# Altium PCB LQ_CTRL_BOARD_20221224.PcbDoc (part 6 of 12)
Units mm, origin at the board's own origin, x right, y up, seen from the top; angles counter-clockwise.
Board outline 260 x 142 mm, 6 copper layers (Top Layer, Mid-Layer 1, Mid-Layer 2, Mid-Layer 3, Mid-Layer 4, Bottom Layer); 1105 components, 1039 nets, 3898 pads, 1277 vias.
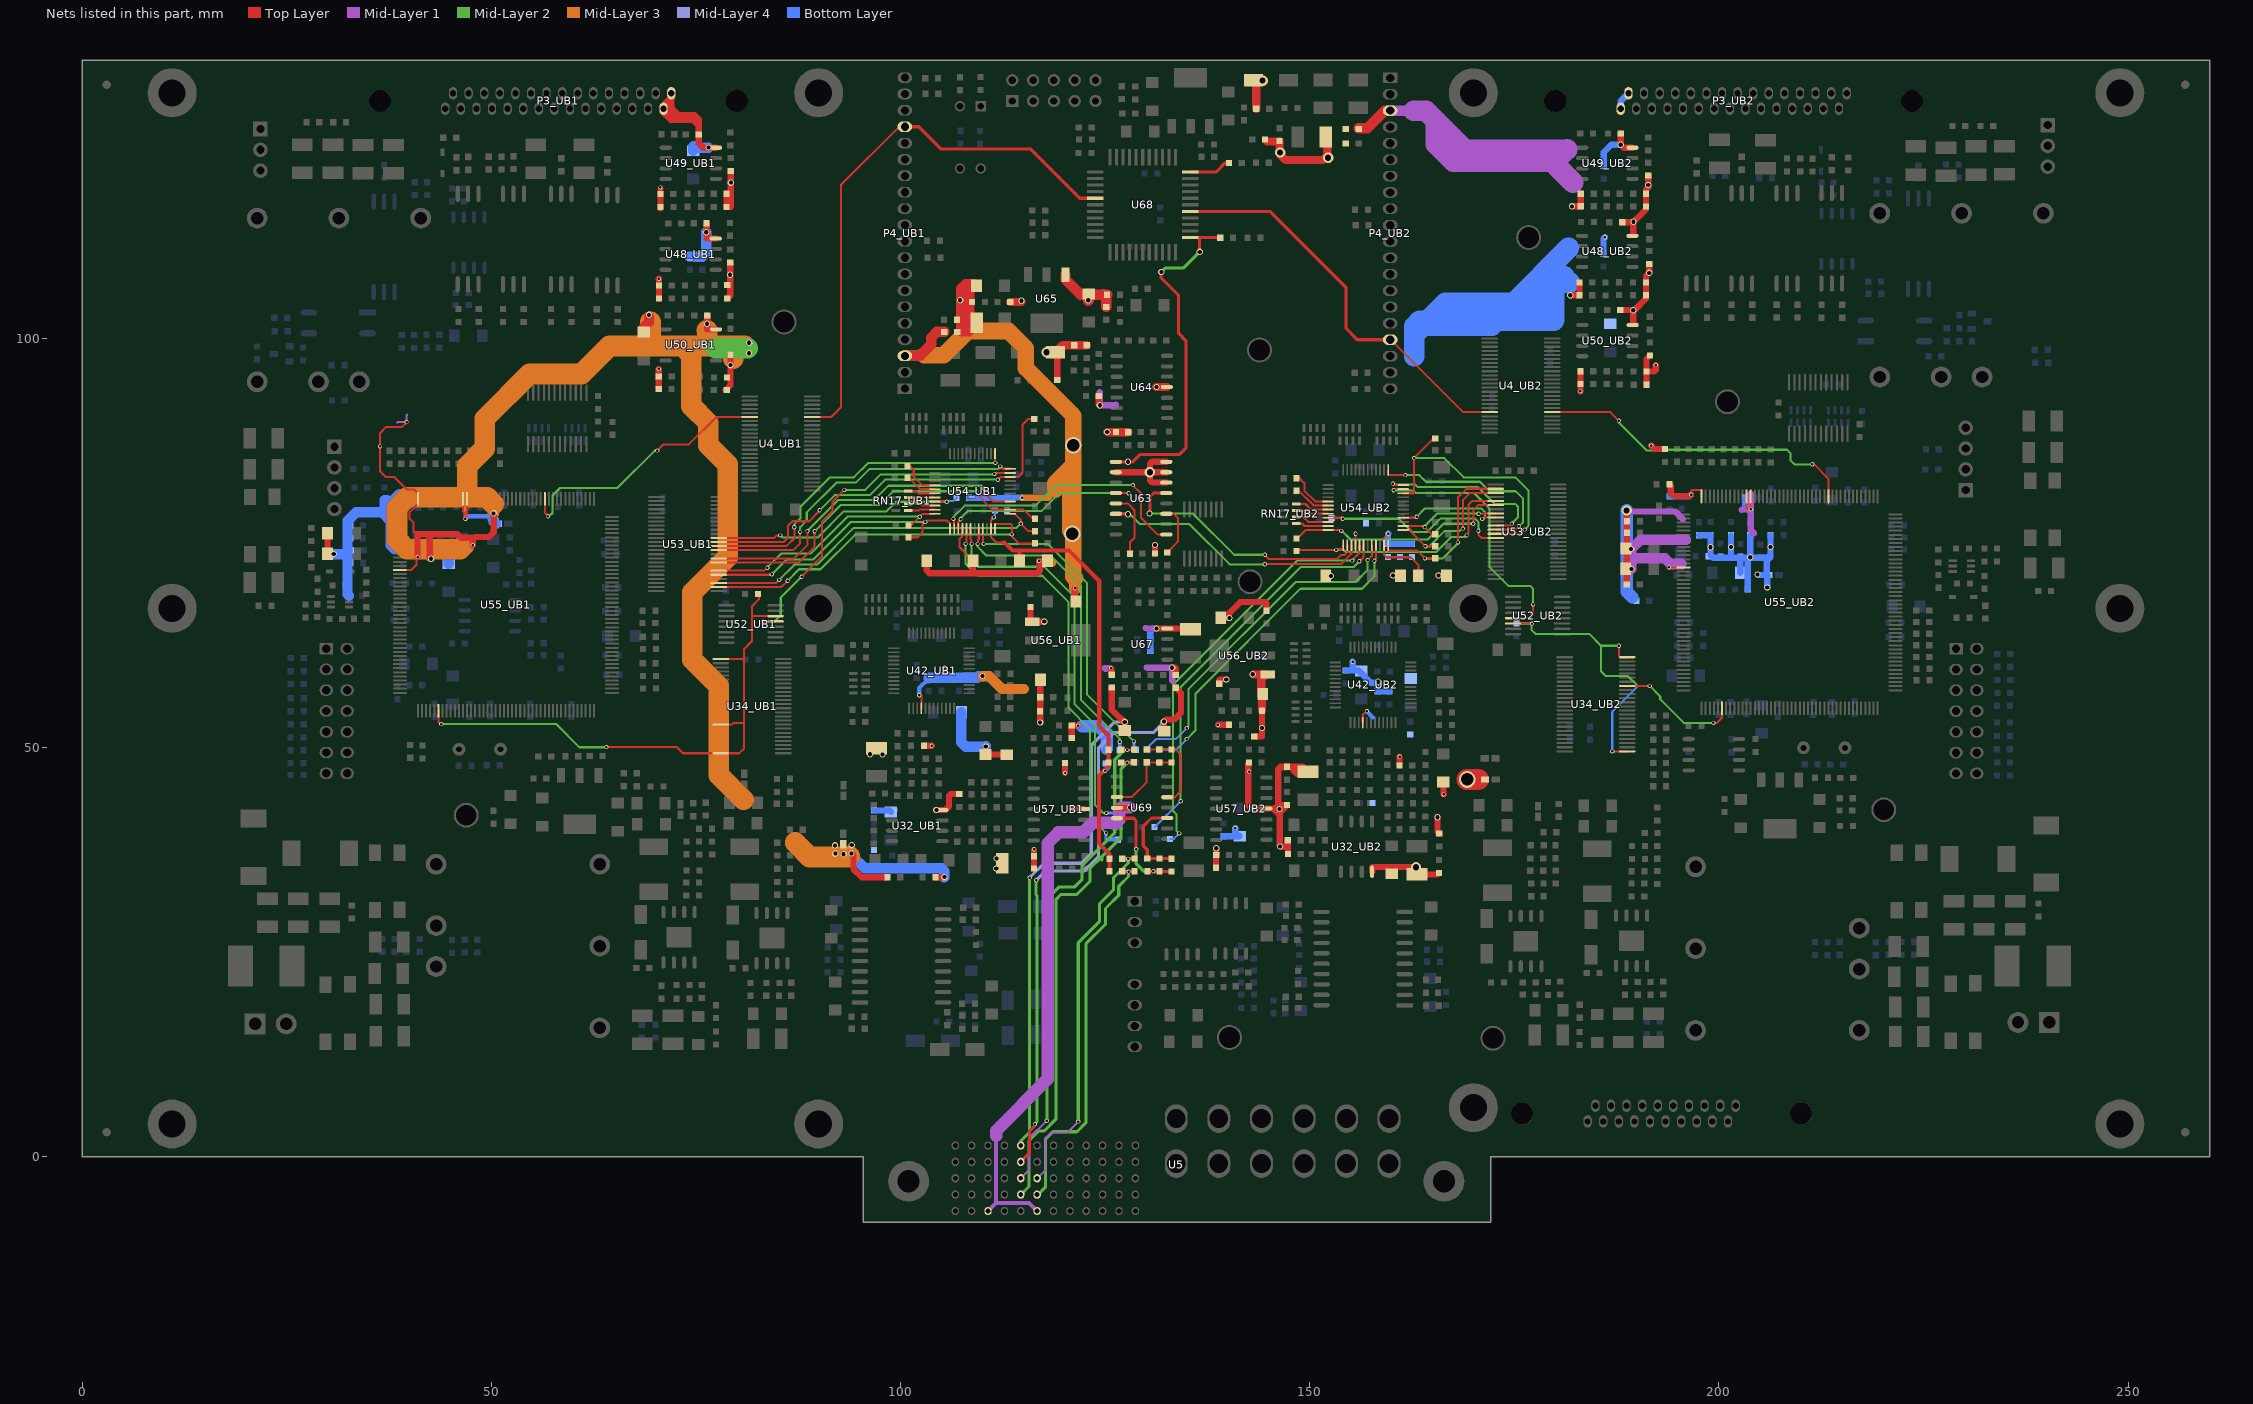
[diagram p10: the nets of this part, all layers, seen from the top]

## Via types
v1: diameter 0.508, hole 0.305, Top Layer to Bottom Layer, 845 vias
v2: diameter 0.762, hole 0.508, Top Layer to Bottom Layer, 317 vias
v3: diameter 1.27, hole 0.762, Top Layer to Bottom Layer, 77 vias
v4: diameter 2.032, hole 1.524, Top Layer to Bottom Layer, 15 vias
v5: diameter 2.032, hole 1.27, Top Layer to Bottom Layer, 11 vias
v6: diameter 1.27, hole 0.711, Top Layer to Bottom Layer, 8 vias
v7: diameter 2.54, hole 1.778, Top Layer to Bottom Layer, 3 vias
v8: diameter 1.524, hole 1.016, Top Layer to Bottom Layer, 1 vias

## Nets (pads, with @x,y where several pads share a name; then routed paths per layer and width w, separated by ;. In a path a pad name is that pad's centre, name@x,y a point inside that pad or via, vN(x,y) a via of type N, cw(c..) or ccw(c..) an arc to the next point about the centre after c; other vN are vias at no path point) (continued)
AGND_UB1: C1_UB1.1 C2_UB1.1 C242_UB1.2 C259_UB1.2 C260_UB1.2 C261_UB1.2 C262_UB1.2 C267_UB1.2 C268_UB1.2 C284_UB1.2 C285_UB1.1 C286_UB1.2 C287_UB1.2 C288_UB1.2 C289_UB1.2 C299_UB1.1 C300_UB1.1 C301_UB1.1 C302_UB1.1 C303_UB1.1 C304_UB1.1 C311_UB1.2 C312_UB1.2 C319_UB1.1 C324_UB1.1 C325_UB1.1 C326_UB1.1 C327_UB1.2 C328_UB1.2 C329_UB1.1 C330_UB1.1 C343_UB1.1 C344_UB1.1 C345_UB1.1 C354_UB1.1 C355_UB1.1 C360_UB1.1 C361_UB1.1 C362_UB1.2 C363_UB1.2 C364_UB1.2 C365_UB1.2 C369_UB1.2 C370_UB1.2 C371_UB1.1 C372_UB1.1 C373_UB1.2 C374_UB1.1 C377_UB1.2 C378_UB1.2 C379_UB1.2 C380_UB1.2 C381_UB1.2 C382_UB1.2 C389_UB1.2 C392_UB1.2 C393_UB1.2 C394_UB1.2 C395_UB1.2 C396_UB1.2 C397_UB1.2 C398_UB1.2 C399_UB1.2 C400_UB1.2 P3_UB1.15 P3_UB1.30 P4_UB1.3 R17_UB1.2 R18_UB1.2 R19_UB1.2 R20_UB1.2 R21_UB1.2 R22_UB1.2 R198_UB1.1 R216_UB1.2 R231_UB1.1 R296_UB1.1 R299_UB1.2 R325_UB1.1 R328_UB1.1 R330_UB1.1 R341_UB1.1 R342_UB1.1 R343_UB1.2 R344_UB1.2 R386.1 U32_UB1.4 U42_UB1.40 U48_UB1.4 U49_UB1.4 U50_UB1.4 U54_UB1.40 U55_UB1.32 U55_UB1.33 U55_UB1.44 U55_UB1.58 U56_UB1.1 U57_UB1.11 | length 534.2
  Top Layer w0.254: U55_UB1.58@38.84,71.691 40.22,71.691 40.869,72.339 v1@40.869,73.279 ; v1@39.7,89.764 39.116,89.179 37.16,89.179 36.398,88.417 36.398,83.769 37.135,83.033 38.176,83.033 39.7,81.509 40.589,81.509 ; 40.589,81.534 40.589,81.509 ; U55_UB1.44@41.04,79.674 U55_UB1.44@41.04,79.775 ; U55_UB1.33@46.54,80.391 46.533,80.384 46.533,78.867 46.711,78.689 ; 46.66,78.689 46.711,78.689 ; v1@46.838,77.851 v1(46.838,77.927) 46.838,78.638 ; U55_UB1.32@47.04,80.391 47.04,78.702 47.027,78.689 46.711,78.689 ; v1(102.286,56.394) 102.301,56.379 102.549,56.379 U42_UB1.40@102.549,54.785 ; U54_UB1.40@107.563,76.71 107.563,75.839 107.213,75.489 107.213,74.498 108.864,72.847 C369_UB1.2@108.864,72.822 ; 40.589,81.509 41.04,81.058 U55_UB1.44@41.04,80.391 U55_UB1.44@41.04,79.775 ; v1@40.869,73.279 40.869,76.098 40.97,76.2 ; v1@40.869,73.279 40.97,73.381 40.97,76.2 ; 40.97,76.2 40.97,76.302 ; 40.97,76.2 41.021,76.251 40.97,76.302 ; 40.97,76.302 40.513,76.302 40.513,77.445 40.02,77.937 40.02,78.755 U55_UB1.44@41.04,79.775
  Top Layer w0.762: C381_UB1.2@29.98,73.66 C382_UB1.2@29.98,76.2 ; C381_UB1.2@30.142,73.635 v2(30.759,73.635) ; v1(40.996,73.279) 40.996,75.87 41.173,76.048 42.494,76.048 ; v2(42.621,73.076) 42.494,73.203 42.494,76.048 ; v1(47.727,74.727) 47.727,75.387 47.981,75.641 ; v2(50.292,78.613) 50.292,76.302 49.708,75.717 48.057,75.717 47.981,75.641 ; v1(70.46,96.266) 70.465,96.261 R19_UB1.2@70.465,95.326 C301_UB1.1@70.465,93.878 ; v1@70.465,107.29 v1(70.485,107.27) R21_UB1.2@70.485,106.451 C299_UB1.1@70.485,104.877 ; C324_UB1.1@70.663,115.875 v1@70.663,118.237 ; C324_UB1.1@70.663,116.078 C324_UB1.1@70.688,116.053 ; P3_UB1.15@71.044,128.047 71.044,127.584 71.323,127.305 ; P3_UB1.30@71.996,129.952 P3_UB1.30@71.996,129.464 ; C302_UB1.1@76.332,114.071 76.332,112.192 U48_UB1.4@77.425,112.192 ; C304_UB1.1@76.403,102.794 76.403,101.092 U50_UB1.4@77.45,101.092 ; v2(76.53,123.302) v2@76.54,123.292 ; U49_UB1.4@77.472,123.302 U49_UB1.4@77.462,123.292 v2@76.54,123.292 ; C325_UB1.1@78.644,93.675 79.223,94.254 v2(79.223,96.723) C330_UB1.1@79.223,97.993 ; C319_UB1.1@78.842,104.877 79.197,105.232 C326_UB1.1@79.197,109.271 ; 79.273,117.856 C303_UB1.1@79.273,120.447 ; v2(94.021,37.059) 94.259,36.82 94.259,35.154 95.275,34.138 R216_UB1.2@98.389,34.138 ; C242_UB1.2@102.87,50.216 v1(103.81,50.216) ; C373_UB1.2@103.2,72.796 103.2,71.646 103.549,71.298 108.966,71.298 ; R198_UB1.1@104.267,34.163 v2(105.359,34.163) ; U32_UB1.4@104.383,42.367 U32_UB1.4@105.12,42.367 105.475,42.367 105.933,42.824 105.933,44.134 106.121,44.323 C261_UB1.2@107.188,44.323 ; C369_UB1.2@108.864,72.822 108.864,71.399 108.966,71.298 ; v2(110.414,50.14) 110.388,50.114 C267_UB1.2@110.388,49.149 112.986,49.149 C259_UB1.2@113.011,49.124 ; C395_UB1.2@115.895,67.183 115.895,65.583 U56_UB1.1@116.098,65.38 v2(117.577,65.38) ; R343_UB1.2@116.307,35.204 v1@116.307,37.465 ; v1(116.942,72.801) v1@116.946,72.796 ; v2(117.069,53.061) 117.089,53.081 C396_UB1.2@117.089,56.134 C394_UB1.2@117.089,58.293 ; C362_UB1.2@117.958,72.796 v1@116.946,72.796 ; v1(120.117,46.888) R344_UB1.2@120.117,48.108 ; R341_UB1.1@120.929,51.156 C397_UB1.2@120.929,52.68 v1(121.717,52.68) ; v1(121.082,42.52) 121.107,42.494 U57_UB1.11@122.423,42.494 ; v1@121.285,69.367 121.285,67.965 C393_UB1.2@121.407,67.843 ; 42.494,76.048 45.872,76.048 46.279,75.641 47.981,75.641 ; 71.323,127.305 71.323,128.791 P3_UB1.30@71.996,129.464 ; 71.323,127.305 71.933,126.695 72.492,126.695 ; 71.996,128.156 71.996,127.191 72.492,126.695 ; 71.996,128.156 P3_UB1.30@71.996,129.464 ; 71.996,128.156 72.898,127.254 74.835,127.254 ; 72.492,126.695 74.835,126.695 ; 74.835,126.695 74.835,127.254 ; 74.835,126.695 74.835,126.511 75.342,126.004 ; 74.835,126.695 75.089,126.695 75.342,126.442 ; 74.835,127.254 75.342,126.747 75.342,126.442 ; 75.342,126.004 75.342,126.442 ; 75.342,126.004 C329_UB1.1@75.342,124.917 75.342,123.845 75.895,123.292 v2@76.54,123.292 ; 108.966,71.298 116.713,71.298 117.018,71.603 117.018,72.725 v1@116.946,72.796 ; C300_UB1.1@78.745,116.053 R17_UB1.2@78.745,117.678 79.273,117.678 79.299,117.704 79.299,116.103 79.248,116.053 C300_UB1.1@78.745,116.053
  Top Layer w1.27: C312_UB1.2@68.605,100.762 68.605,101.295 69.266,101.956 v2@69.266,102.616 ; P4_UB1.3@100.533,97.853 102.349,97.853 103.759,99.263 103.759,100.101 104.445,100.787 R386.1@105.359,100.787
  Mid-Layer 1 w0.254: 38.506,89.713 38.557,89.764 v1(39.649,89.764) 39.649,90.627 39.7,90.678 39.7,90.703
  Mid-Layer 2 w2.54: 77.445,98.781 81.305,98.781
  Mid-Layer 3 w0.508: v1(46.838,77.927) 46.838,79.604 47.828,80.594
  Mid-Layer 3 w0.762: v1(114.859,80.518) 118.11,80.518 118.161,80.569 ; v1(116.942,72.801) 118.36,72.801 118.643,72.517
  Mid-Layer 3 w1.27: v2(50.292,78.613) 50.292,79.766 ; P4_UB1.3@100.533,97.853 102.806,97.853 102.895,97.942 ; v2(110.033,58.725) 110.846,58.725 112.42,57.15 115.062,57.15
  Mid-Layer 3 w1.524: 121.107,84.48 121.082,84.455 121.082,82.372 120.498,81.788 120.498,78.858 ; v1(121.336,69.444) 121.336,70.663 v4@121.336,75.565 ; 120.498,78.858 121.107,78.248 121.336,78.02 v4@121.336,75.565 ; 120.498,78.858 120.498,76.403 121.107,75.794 v4@121.336,75.565
  Mid-Layer 3 w2.032: 102.895,97.942 105.308,97.942 108.255,100.889 113.208,100.889 115.316,98.781 115.316,96.342 121.107,90.551 121.107,84.48 121.107,82.398 ; 118.897,81.509 118.897,82.271 121.082,84.455 ; 121.082,82.372 121.107,82.398 ; 121.336,70.663 121.107,70.891 121.107,75.794 121.107,78.248 121.107,82.398
  Mid-Layer 3 w2.54: 46.702,74.727 46.204,74.229 39.665,74.229 38.481,75.413 38.481,79.299 39.776,80.594 47.828,80.594 ; 49.062,86.447 49.062,86.4 ; 50.292,79.766 49.464,80.594 47.828,80.594 ; 69.444,101.981 69.444,99.162 69.342,99.06 ; 76.352,100.94 76.378,100.914 76.378,99.06 ; 79.578,97.536 79.578,98.349 78.867,99.06 ; 80.823,43.612 77.8,46.634 77.8,57.506 74.549,60.757 74.549,68.936 78.892,73.279 78.892,84.582 76.505,86.97 76.505,89.687 74.447,91.745 74.447,97.997 73.99,98.455 73.99,99.06 ; 81.026,99.009 80.975,99.06 78.867,99.06 ; 87.147,38.379 88.9,36.627 93.675,36.627 93.777,36.728 ; 47.828,80.594 47.066,81.356 47.066,84.404 49.062,86.4 ; 49.062,86.4 49.2,86.538 49.2,90.17 54.686,95.656 61.036,95.656 64.44,99.06 69.342,99.06 ; 69.342,99.06 73.99,99.06 ; 73.99,99.06 76.378,99.06 ; 76.378,99.06 78.867,99.06
  Bottom Layer w0.508: v1(46.838,77.927) 46.838,77.953 47.142,78.257 49.733,78.257 v2@50.19,78.715 ; v1(102.286,56.394) 102.286,57.252 103.429,58.395 C285_UB1.1@103.429,58.471 ; C268_UB1.2@105.004,58.522 105.385,58.903 v1(105.385,59.754)
  Bottom Layer w0.762: C355_UB1.1@40.97,74.041 C355_UB1.1@40.742,74.27 C355_UB1.1@40.996,74.27 ; v1@40.996,73.381 C355_UB1.1@40.996,74.27 ; 42.621,74.27 C372_UB1.1@42.24,74.27 C355_UB1.1@40.996,74.27 ; 42.774,74.27 44.907,74.27 45.187,74.27 C1_UB1.1@45.212,74.295 ; C400_UB1.2@46.761,74.295 46.761,74.346 47.092,74.676 v1@47.6,74.676 ; C287_UB1.2@96.774,42.291 98.679,42.291 C289_UB1.2@98.831,42.139 ; C374_UB1.1@108.382,80.518 108.42,80.48 112.967,80.48 C364_UB1.2@113.03,80.543 114.833,80.543 v1(114.859,80.518)
  Bottom Layer w1.27: v2(30.759,73.635) 32.436,73.635 ; R299_UB1.2@32.614,68.555 32.436,68.732 32.436,73.635 ; 37.719,79.888 38.781,80.95 R328_UB1.1@39.7,80.95 ; R328_UB1.1@39.548,80.874 C361_UB1.1@41.072,80.874 46.126,80.874 ; v2@42.621,73.33 42.621,74.27 ; C398_UB1.2@44.78,72.466 44.78,74.143 44.907,74.27 C1_UB1.1@44.933,74.295 ; C2_UB1.1@45.695,80.95 48.616,80.95 C345_UB1.1@48.666,80.899 49.784,80.899 50.19,80.493 50.19,78.715 v2(50.292,78.613) ; C400_UB1.2@46.761,74.295 C1_UB1.1@45.212,74.295 C1_UB1.1@44.933,74.295 ; v2@50.19,78.384 50.19,77.95 50.292,77.848 50.292,77.607 R296_UB1.1@50.543,77.356 ; C328_UB1.2@74.27,109.957 C327_UB1.2@75.783,109.957 76.276,110.45 v2(76.276,112.954) ; C311_UB1.2@74.651,122.911 74.651,123.393 74.727,123.469 74.894,123.302 v2(76.53,123.302) ; 92.329,36.703 94.158,36.703 94.158,36.678 95.606,35.23 C377_UB1.2@98.984,35.23 C378_UB1.2@100.508,35.23 105.004,35.23 105.359,34.874 v2(105.359,34.163) ; C285_UB1.1@103.429,58.471 103.48,58.522 C268_UB1.2@105.004,58.522 C262_UB1.2@107.137,58.522 C260_UB1.2@108.56,58.522 109.372,58.522 109.576,58.725 v2(110.033,58.725) ; C284_UB1.2@107.442,54.331 107.442,50.622 107.95,50.114 110.388,50.114 v2(110.414,50.14) ; 32.436,73.635 32.436,77.699 33.477,78.74 36.652,78.74 ; 36.652,78.74 37.719,77.673 ; 36.652,78.74 36.703,78.74 ; 36.703,78.74 37.059,78.74 ; 36.703,78.74 36.957,78.994 ; 36.957,78.994 36.957,78.842 37.059,78.74 ; 36.957,78.994 C343_UB1.1@36.957,80.213 37.262,80.213 37.719,79.756 ; 36.957,78.994 37.719,79.756 ; 37.059,78.74 37.719,79.4 ; 37.719,77.673 37.719,74.727 38.151,74.295 C360_UB1.1@43.713,74.295 C1_UB1.1@44.933,74.295 ; 37.719,77.673 37.719,79.4 ; 37.719,79.4 37.719,79.756
  Bottom Layer w1.524: 122.225,52.578 124.206,52.578 125.222,51.562 C365_UB1.2@125.222,49.86
  other v1: 116.332,37.567 36.424,86.792 70.663,118.44
  other v2: 111.709,35.23 111.749,36.437 93.055,36.957 92.039,37.033 92.014,38.049 94.046,38.075 104.383,42.381 97.79,49.149 96.266,49.174 81.483,98.171 81.509,99.466 76.352,101.778 69.266,102.87 79.172,107.772 79.273,119.024
  other v4: 121.006,76.123 121.133,86.919
AGND_UB2: C1_UB2.1 C2_UB2.1 C242_UB2.2 C259_UB2.2 C260_UB2.2 C261_UB2.2 C262_UB2.2 C267_UB2.2 C268_UB2.2 C284_UB2.2 C285_UB2.1 C286_UB2.2 C287_UB2.2 C288_UB2.2 C289_UB2.2 C299_UB2.1 C300_UB2.1 C301_UB2.1 C302_UB2.1 C303_UB2.1 C304_UB2.1 C311_UB2.2 C312_UB2.2 C319_UB2.1 C324_UB2.1 C325_UB2.1 C326_UB2.1 C327_UB2.2 C328_UB2.2 C329_UB2.1 C330_UB2.1 C343_UB2.1 C344_UB2.1 C345_UB2.1 C354_UB2.1 C355_UB2.1 C360_UB2.1 C361_UB2.1 C362_UB2.2 C363_UB2.2 C364_UB2.2 C365_UB2.2 C369_UB2.2 C370_UB2.2 C371_UB2.1 C372_UB2.1 C373_UB2.2 C374_UB2.1 C377_UB2.2 C378_UB2.2 C379_UB2.2 C380_UB2.2 C381_UB2.2 C382_UB2.2 C389_UB2.2 C392_UB2.2 C393_UB2.2 C394_UB2.2 C395_UB2.2 C396_UB2.2 C397_UB2.2 C398_UB2.2 C399_UB2.2 C400_UB2.2 P3_UB2.15 P3_UB2.30 P4_UB2.3 R17_UB2.2 R18_UB2.2 R19_UB2.2 R20_UB2.2 R21_UB2.2 R22_UB2.2 R198_UB2.1 R216_UB2.2 R231_UB2.1 R296_UB2.1 R299_UB2.2 R325_UB2.1 R328_UB2.1 R330_UB2.1 R341_UB2.1 R342_UB2.1 R343_UB2.2 R344_UB2.2 R388.1 U32_UB2.4 U42_UB2.40 U48_UB2.4 U49_UB2.4 U50_UB2.4 U54_UB2.40 U55_UB2.32 U55_UB2.33 U55_UB2.44 U55_UB2.58 U56_UB2.1 U57_UB2.11 | length 358.7
  Top Layer w0.254: U54_UB2.40@155.592,74.723 155.592,76.115 v1(155.6,76.123) ; U42_UB2.40@156.484,53.05 156.484,53.969 v1@156.947,54.432 ; v1@193.806,72.009 v1(193.904,72.009) U55_UB2.58@195.605,72.009 ; v1(196.596,80.899) 196.596,81.331 196.748,81.483 197.815,81.483 197.885,81.413 U55_UB2.44@197.885,80.696 ; U55_UB2.33@203.385,80.696 203.385,79.291 203.606,79.07 203.632,79.096 v1@203.911,79.096 ; U55_UB2.32@203.885,80.696 203.885,79.122 v1@203.911,79.096 ; v1@203.937,79.121 v1@203.911,79.096
  Top Layer w0.762: R343_UB2.2@138.557,35.306 138.557,36.83 R342_UB2.1@138.582,36.855 v2(138.582,37.694) ; v1(138.786,52.756) 138.811,52.781 C397_UB2.2@140.157,52.781 ; C396_UB2.2@138.938,57.785 138.938,58.191 139.048,58.301 v2(139.802,58.301) ; C393_UB2.2@139.13,65.862 v2@140.157,65.862 ; v2(140.183,65.837) v2@140.157,65.862 ; R344_UB2.2@142.596,48.184 142.494,48.082 142.494,42.875 142.824,42.545 v1(143.358,42.545) U57_UB2.11@144.704,42.545 145.542,42.545 ; R341_UB2.1@143.231,51.333 144.145,51.333 144.17,51.359 R330_UB2.1@144.17,54.487 ; C395_UB2.2@144.729,66.726 144.729,67.64 144.602,67.767 141.503,67.767 140.157,66.421 v2@140.157,65.862 ; v2(146.304,42.494) v2@146.253,42.545 ; R216_UB2.2@147.32,38.659 147.345,38.633 147.345,37.871 ; R198_UB2.1@147.345,36.982 147.345,37.871 ; U32_UB2.4@157.632,34.823 157.632,35.331 157.709,35.408 162.839,35.408 162.865,35.433 163.119,35.179 C288_UB2.2@163.119,34.493 165.633,34.493 C286_UB2.2@165.811,34.671 ; v2@160.147,71.044 v2(160.173,71.018) C369_UB2.2@161.112,71.018 ; C242_UB2.2@160.96,47.803 160.96,48.92 v1(160.985,48.895) ; v2(165.608,41.478) 165.608,39.726 C287_UB2.2@165.837,39.497 ; v2@165.71,71.044 v2(165.735,71.018) C362_UB2.2@166.7,71.018 ; C267_UB2.2@166.345,45.771 166.345,44.298 v1(166.37,44.272) ; v2(181.839,105.258) C299_UB2.1@182.956,105.258 R21_UB2.2@182.956,106.807 ; v2@182.27,116.129 C324_UB2.1@183.134,116.129 R18_UB2.2@183.134,117.653 ; R19_UB2.2@183.07,95.987 183.083,95.973 C301_UB2.1@183.083,94.412 v1(183.083,93.523) ; C304_UB2.1@187.935,103.454 189.687,103.454 191.084,104.851 C319_UB2.1@191.084,105.258 R22_UB2.2@191.084,106.832 191.084,107.594 v2(191.491,108.001) C326_UB2.1@191.491,109.093 ; C329_UB2.1@188.011,125.019 v2(188.011,123.647) 188.366,123.292 U49_UB2.4@189.459,123.292 ; C302_UB2.1@188.189,114.198 v2@189.535,114.198 ; v3@188.722,78.842 188.747,78.816 C380_UB2.2@188.747,69.926 ; U50_UB2.4@189.535,101.854 v2@189.535,103.378 ; U48_UB2.4@189.535,112.751 v2@189.535,114.198 ; R20_UB2.2@191.147,95.936 R20_UB2.2@191.16,95.936 ; C325_UB2.1@191.16,94.336 R20_UB2.2@191.16,95.936 ; C303_UB2.1@191.364,119.888 191.364,118.44 191.11,118.186 R17_UB2.2@191.11,117.653 C300_UB2.1@191.11,116.103 191.11,115.773 v2@189.535,114.198 ; C330_UB2.1@191.592,97.917 191.16,97.485 R20_UB2.2@191.16,95.936 ; v1(191.745,86.893) 192.176,86.462 R328_UB2.1@193.421,86.462 ; v1(192.278,96.723) 192.278,96.139 192.075,95.936 R20_UB2.2@191.16,95.936 ; C343_UB2.1@193.954,82.169 194.107,82.017 194.107,81.077 194.462,80.721 196.418,80.721 v1(196.596,80.899) ; 145.542,42.545 145.72,42.545 ; 145.542,42.545 146.329,41.758 ; 145.72,42.545 v2@146.152,42.545 ; 145.72,42.545 146.152,42.977 ; v2@146.152,42.545 v2@146.253,42.545 ; v2@146.152,42.545 146.152,42.977 ; 146.152,42.977 146.152,47.371 146.329,47.549 ; 146.152,42.977 C378_UB2.2@147.244,42.977 146.812,42.545 ; v2@146.253,42.545 146.812,42.545 ; 146.329,41.758 146.329,38.049 146.507,37.871 147.345,37.871 ; 146.329,41.758 146.329,42.062 146.812,42.545 ; 146.329,47.549 147.142,47.549 C377_UB2.2@147.244,47.65 ; 146.329,47.549 146.431,47.65 C377_UB2.2@147.244,47.65 ; C377_UB2.2@147.244,47.65 C377_UB2.2@147.599,47.65 ; C377_UB2.2@147.599,47.65 148.488,46.761 148.768,47.041 C379_UB2.2@149.784,47.041 149.174,47.65 C377_UB2.2@147.599,47.65
  Top Layer w1.016: v2@143.154,58.928 U56_UB2.1@144.653,58.928 ; C394_UB2.2@144.094,56.363 144.094,58.369 U56_UB2.1@144.653,58.928 ; R330_UB2.1@144.17,54.487 144.17,56.439 C394_UB2.2@144.272,56.54 ; U56_UB2.1@144.882,58.928 U56_UB2.1@144.653,58.928
  Top Layer w1.27: R388.1@155.981,125.679 157.023,125.679 159.156,127.813 P4_UB2.3@159.601,127.813
  Top Layer w2.54: v4(169.24,46.101) 170.612,46.101
  Mid-Layer 1 w0.508: v1(193.904,72.009) 195.605,72.009 195.656,72.06
  Mid-Layer 1 w0.762: v3@188.722,78.842 194.666,78.842 195.58,77.927 ; 202.794,79.045 202.835,79.087 v1(203.886,79.087) ; 203.886,81.001 v1(203.886,79.087) ; 204.292,76.174 203.886,76.581 v1(203.886,79.087)
  Mid-Layer 1 w1.27: P4_UB2.3@159.842,127.826 162.75,127.826 162.763,127.813 ; v2(189.281,74.27) v2@189.306,74.244 ; v2(189.306,71.831) 189.306,73.228 ; 195.428,72.466 194.056,72.466 193.396,73.127 189.408,73.127 189.306,73.228 ; 195.961,75.413 190.424,75.413 189.306,74.295 v2@189.306,74.244 ; 189.306,73.228 v2@189.306,74.244
  Mid-Layer 1 w2.54: 162.763,127.813 164.211,127.813 165.43,126.594 ; 181.432,123.088 181.356,123.012 ; 182.169,119.05 179.629,121.59 ; 165.43,124.282 165.43,123.723 166.7,122.453 ; 165.43,124.282 166.7,123.012 ; 165.43,124.282 165.43,126.594 ; 165.43,126.594 169.012,123.012 ; 166.7,122.453 167.564,121.59 179.629,121.59 ; 166.7,122.453 166.7,123.012 ; 166.7,123.012 169.012,123.012 ; 169.012,123.012 181.356,123.012 ; 179.629,121.59 179.934,121.59 181.356,123.012
  Bottom Layer w0.508: v1(156.997,54.458) 156.997,54.381 157.709,53.67
  Bottom Layer w0.762: C327_UB2.2@139.471,39.155 141.415,39.155 C284_UB2.2@141.427,39.167 140.919,39.675 v1(140.919,40.157) ; C328_UB2.2@154.381,59.411 155.27,59.411 ; v1(155.245,60.477) 155.245,60.452 155.27,60.427 155.27,59.411 ; C260_UB2.2@159.741,56.845 C268_UB2.2@158.293,56.845 158.293,57.683 158.064,57.912 157.48,57.912 155.981,59.411 155.27,59.411 ; 181.762,106.832 181.839,106.756 v2(181.839,105.258) ; C374_UB2.1@185.903,110.338 185.903,112.166 v1(186.08,112.344) ; C285_UB2.1@185.928,121.082 185.928,122.733 186.842,123.647 v2(188.011,123.647) ; P3_UB2.30@188.001,128.047 188.001,129 P3_UB2.15@188.953,129.952 ; C345_UB2.1@193.954,80.696 196.393,80.696 v1(196.596,80.899) ; C355_UB2.1@197.561,75.946 198.958,75.946 C361_UB2.1@198.984,75.971 198.984,73.482 199.288,73.177 201.473,73.177 ; C354_UB2.1@201.473,75.921 201.473,73.177 ; C398_UB2.2@202.616,71.349 202.616,73.127 C360_UB2.1@202.565,73.177 ; C399_UB2.2@203.225,80.543 203.225,79.324 203.463,79.087 v1(203.886,79.087) ; C400_UB2.2@203.53,69.317 203.53,72.949 v2@203.759,73.177 ; C371_UB2.1@203.835,75.87 v2(203.835,73.254) ; v2@204.775,71.095 204.8,71.069 R296_UB2.1@205.918,71.069 ; C1_UB2.1@205.054,73.228 C1_UB2.1@205.003,73.177 ; v2(205.918,69.545) R296_UB2.1@205.918,71.069 ; C2_UB2.1@206.299,75.971 v2(206.299,74.498) 206.299,73.558 ; 201.473,73.177 C360_UB2.1@202.565,73.177 ; C360_UB2.1@202.565,73.177 v2@203.759,73.177 ; v2@203.759,73.177 v2@203.911,73.177 ; v2@203.759,73.177 v2(203.835,73.254) ; v2(203.835,73.254) v2@203.911,73.177 ; v2@203.911,73.177 C1_UB2.1@205.003,73.177 ; C1_UB2.1@205.003,73.177 205.918,73.177 206.299,73.558 ; R296_UB2.1@205.918,71.069 205.842,71.145 205.842,72.771 206.299,73.228 206.299,73.558
  Bottom Layer w1.524: v3(188.722,78.969) 188.722,69.063 189.408,68.377
  Bottom Layer w2.54: 162.789,97.853 162.789,100.508 ; 176.555,102.997 179.883,106.324 ; 181.102,107.544 180.391,106.832 ; 181.635,111.023 174.93,104.318 166.599,104.318 164.44,102.159 ; 181.762,106.832 180.391,106.832 ; 162.789,100.508 162.789,101.473 162.89,101.575 ; 162.789,100.508 163.855,101.575 ; 162.89,101.575 163.855,101.575 ; 162.89,101.575 163.474,102.159 164.44,102.159 ; 163.855,101.575 172.237,101.575 172.822,102.159 ; 163.855,101.575 164.44,102.159 ; 164.44,102.159 172.822,102.159 ; 172.822,102.159 179.781,102.159 179.883,102.26 179.883,106.324 ; 179.883,106.324 179.883,106.705 180.01,106.832 180.391,106.832 ; 179.883,106.324 180.391,106.832
  other v1: 142.596,47.066
  other v2: 146.38,37.897 144.17,52.375 158.344,58.039 143.053,58.953 152.603,70.967 204.724,71.145 198.984,74.473 201.473,74.498 189.535,103.429 189.56,114.249 182.042,116.129 191.364,118.745
  other v3: 162.992,35.382
AGNDMS: C424.2 C425.2 C426.2 C427.2 C428.2 C429.2 C430.2 C431.2 C432.2 C433.2 C434.2 C435.2 C444.2 DR3.2 DR4.2 R1.2 R2.2 R377.2 R382.1 R383.1 R384.2 R385.2 R386.2 R387.2 R388.2 R389.1 R390.1 R398.1 R405.2 U5.A3 U5.A6 U63.6 U63.7 U63.8 U63.10 U64.11 U65.1 U67.4 U69.11 | length 156.2
  Top Layer w0.762: DR4.2@118.956,98.298 119.151,98.102 R377.2@119.151,94.894 ; R385.2@124.231,92.964 124.231,92.202 ; 124.257,92.202 124.231,92.202 ; v2(124.358,91.821) 124.231,91.948 124.231,92.202 ; R405.2@125.755,58.953 v1@125.755,59.614 ; U63.10@126.314,83.642 v3(130.48,83.642) ; U69.11@126.447,42.634 128.054,42.634 128.067,42.621 128.067,42.647 v2(128.041,42.672) ; C444.2@131.109,73.723 131.109,74.747 v2(131.115,74.752) ; v2(131.267,64.541) U67.4@132.608,64.541 135.331,64.541 C424.2@135.433,64.44 ; U63.6@132.486,82.372 130.785,82.372 130.48,82.677 v3(130.48,83.642) ; U63.7@132.486,83.642 v3(130.48,83.642) ; U63.8@132.486,84.912 130.734,84.912 130.48,84.658 v3(130.48,83.642) ; v2(133.198,59.741) 133.549,59.741 133.629,59.66 R398.1@133.629,58.877
  Top Layer w1.016: 108.433,105.994 108.839,106.401 C432.2@109.296,106.401 ; C430.2@113.426,104.445 v2@114.783,104.445 ; DR4.2@118.956,98.298 119.819,99.162 C427.2@121.234,99.162 R382.1@122.758,99.162 ; v2(125.273,88.544) 125.324,88.544 125.349,88.519 R383.1@127.838,88.519 ; v2(131.267,94.056) U64.11@132.563,94.056 ; DR3.2@143.122,131.547 143.485,131.184 R387.2@143.485,128.067 ; R389.1@144.78,124.054 146.253,124.054 C431.2@146.304,124.104 146.304,122.555 147.066,121.793 151.638,121.793 152.146,122.301 152.146,124.435 C428.2@151.968,124.612
  Top Layer w1.27: R1.2@107.213,102.235 107.417,102.235 ; 108.331,102.26 108.356,102.235 ; 108.433,105.994 108.433,102.235 ; C429.2@108.636,102.235 108.433,102.235 ; C432.2@108.839,106.401 108.153,106.401 107.95,106.604 ; C432.2@109.296,106.401 109.093,106.604 107.95,106.604 ; U65.1@120.167,107.772 120.167,107.188 122.022,105.334 C433.2@122.987,105.334 ; v2@122.936,104.572 122.987,104.623 C433.2@122.987,105.334 ; C433.2@122.987,105.435 C433.2@122.987,105.334 ; 124.79,105.41 125.146,105.054 C435.2@125.146,103.835 ; R390.1@125.247,105.334 C433.2@122.987,105.334 ; 107.417,102.235 107.417,100.838 108.373,100.838 108.433,100.897 108.433,102.159 ; 107.417,102.235 108.356,102.235 ; 107.417,102.235 107.417,106.07 107.95,106.604 ; 108.356,102.235 108.433,102.159 ; 108.356,102.235 108.433,102.235 ; 108.433,102.159 108.433,102.235
  Mid-Layer 1 w0.508: U5.A3@110.7,-6.627 111.684,-5.643 ; 111.684,2.134 111.684,-5.643 ; U5.A6@116.7,-6.627 115.716,-5.643 111.684,-5.643
  Mid-Layer 1 w0.762: 124.358,93.421 v2(124.358,91.821) 126.289,91.821 126.34,91.872 ; 124.943,59.715 v1@125.527,59.715 ; 125.044,59.614 125.146,59.715 ; 129.972,64.618 130.048,64.541 v2(131.267,64.541) ; 130.099,59.792 130.15,59.741 v2(133.198,59.741) 133.198,58.191 133.223,58.166
  Mid-Layer 1 w1.524: 111.709,2.54 111.709,3.2 117.983,9.474 117.983,38.303 119.304,39.624 122.301,39.624 123.469,40.792 126.34,40.792 126.721,41.173 126.721,42.443 126.949,42.672 v2(128.041,42.672)
  Bottom Layer w0.762: C426.2@130.505,61.798 C425.2@130.505,63.246 130.505,64.16 130.886,64.541 v2(131.267,64.541)
  other v1: 125.73,59.715
  other v2: 114.783,104.597 107.29,104.648 122.936,104.648
  other v3: 117.856,98.298 152.248,122.072 146.38,122.707 144.247,131.496
ARDC_CS_UB1: R230_UB1.1 U34_UB1.25 U34_UB1.41 U34_UB1.48 U52_UB1.14 U55_UB1.94 | length 68.4
  Top Layer w0.254: U55_UB1.94@43.54,54.491 43.54,53.137 43.82,52.857 v1(43.891,52.857) ; v1(64.059,50.063) 72.669,50.063 73.431,49.301 U34_UB1.48@78.054,49.301 80.315,49.301 80.874,49.86 80.874,60.808 ; U34_UB1.41@78.054,52.801 79.395,52.801 79.604,53.01 80.721,53.01 ; U34_UB1.25@78.054,60.801 80.867,60.801 80.874,60.808 ; R230_UB1.1@82.702,68.732 82.702,68.123 81.864,67.285 81.864,66.076 ; U52_UB1.14@84.435,66.076 81.864,66.076 ; 80.874,60.808 80.874,62.027 81.864,63.017 81.864,66.076
  Mid-Layer 2 w0.254: v1(43.891,52.857) 43.866,52.883 57.912,52.883 60.757,50.038 64.033,50.038 v1(64.059,50.063)
ARDC_CS_UB2: R230_UB2.1 U34_UB2.25 U34_UB2.41 U34_UB2.48 U52_UB2.14 U55_UB2.94 | length 56.3
  Top Layer w0.254: U52_UB2.14@174.848,65.156 176.779,65.156 176.784,65.151 177.114,65.151 v1@177.14,65.176 ; v1(186.969,49.536) U34_UB2.25@188.798,49.536 ; v1(187.782,62.433) 187.782,61.214 187.96,61.036 U34_UB2.48@188.798,61.036 ; U34_UB2.41@188.798,57.536 191.542,57.536 v1(191.547,57.531) ; v1(199.339,53.01) 199.339,53.002 199.738,53.002 200.385,53.649 U55_UB2.94@200.385,54.796
  Mid-Layer 2 w0.254: v1(177.165,65.151) 177.089,65.075 177.089,64.389 177.597,63.881 184.175,63.881 185.598,62.459 ; v1(187.782,62.433) 185.623,62.433 185.598,62.459 ; v1(199.339,53.01) 195.707,53.01 192.837,55.88 192.837,56.241 v1(191.547,57.531) 190.094,57.531 188.9,58.725 186.207,58.725 185.598,59.334 185.598,62.459
  Bottom Layer w0.254: R230_UB2.1@175.285,65.176 175.311,65.151 v1(177.165,65.151) ; v1(186.969,49.536) 186.969,54.356 190.144,57.531 v1(191.547,57.531)
B_COS+': R419.2 U54_UB1.45 | length 39.1
  Top Layer w0.254: v1@110.02,74.93 110.063,74.973 U54_UB1.45@110.063,76.71
  Mid-Layer 2 w0.254: v1(110.16,74.879) 117.983,74.879 122.809,70.053 122.809,56.464 v1(128.524,50.749)
  Bottom Layer w0.381: R419.2@128.524,49.733 v1(128.524,50.749)
B_COS+'_UB2: R420.2 U54_UB2.45 | length 41.6
  Top Layer w0.254: v1(157.912,72.821) 157.912,72.872 158.092,73.053 U54_UB2.45@158.092,74.723
  Mid-Layer 2 w0.254: v1(134.95,51.029) 134.976,51.029 136.042,52.095 136.042,56.591 148.856,69.405 156.4,69.405 157.912,70.917 v1(157.912,72.821)
  Bottom Layer w0.254: R420.2@131.648,49.759 133.706,49.759 134.976,51.029 v1(134.95,51.029)
B_COS-': R188.2 U54_UB1.44 | length 39
  Top Layer w0.254: v1(109.423,74.879) 109.449,74.879 109.474,74.905 109.474,75.336 109.563,75.426 U54_UB1.44@109.563,76.71
  Mid-Layer 2 w0.254: v1(109.423,74.879) 109.423,74.549 110.515,73.457 118.364,73.457 122.047,69.774 122.047,55.829 126.797,51.079 v1(126.797,50.698)
  Bottom Layer w0.381: R188.2@126.797,49.606 v1(126.797,50.698)
B_COS-'_UB2: R429.2 U54_UB2.44 | length 42
  Top Layer w0.254: v1(157.074,72.898) 157.592,73.416 U54_UB2.44@157.592,74.723
  Mid-Layer 2 w0.254: v1(134.976,52.375) 135.179,52.578 135.179,57.125 148.285,70.231 155.6,70.231 157.074,71.704 v1(157.074,72.898)
  Bottom Layer w0.254: R429.2@130.15,49.759 130.15,49.962 131.216,51.029 133.629,51.029 v1(134.976,52.375)
B_E\X\C\: U54_UB1.39 U63.12 | length 24.8
  Top Layer w0.254: U54_UB1.39@107.063,76.71 107.063,77.574 107.34,77.851 v1(107.34,77.902) ; U63.12@126.314,81.102 127.838,81.102 v1(127.864,81.077)
  Mid-Layer 2 w0.254: v1(107.34,77.902) 107.34,78.003 108.255,78.918 117.246,78.918 119.405,81.077 v1(127.864,81.077)
B_E\X\C\_UB2: U54_UB2.39 U63.14 | length 35.6
  Top Layer w0.254: v1@144.501,72.415 153.843,72.415 154.356,72.929 154.361,72.929 155.092,73.659 U54_UB2.39@155.092,74.723
  Top Layer w0.381: U63.14@126.314,78.562 127.502,78.562 127.533,78.531 127.488,78.531 127.508,78.511 v2(127.787,78.511)
  Mid-Layer 2 w0.254: v2@128.016,78.537 129.235,77.318 135.306,77.318 140.233,72.39 ; 143.027,72.39 140.233,72.39 ; v1(144.501,72.39) 140.233,72.39
B_EXC: U54_UB1.38 U63.1 | length 33.4
  Top Layer w0.254: v1(106.477,77.927) 106.563,77.841 U54_UB1.38@106.563,76.71 ; v1(128.397,82.067) 129.388,81.077 129.388,78.08 131.445,76.022 U63.1@132.486,76.022
  Mid-Layer 2 w0.254: v1(106.477,77.927) 106.477,78.181 107.848,79.553 116.484,79.553 118.999,82.067 v1(128.397,82.067)
B_EXC_UB2: U54_UB2.38 U63.5 | length 31.9
  Top Layer w0.254: v1@144.551,73.508 145.034,73.025 153.326,73.025 153.848,73.546 153.861,73.533 154.273,73.533 154.592,73.852 U54_UB2.38@154.592,74.723
  Top Layer w0.381: v2@130.48,78.613 130.48,80.645 130.937,81.102 U63.5@132.486,81.102
  Mid-Layer 2 w0.254: v2(130.429,78.588) 135.738,78.588 140.767,73.558 v1(144.526,73.558)
B_RDC_A0_UB1: R321_UB1.1 U53_UB1.5 U54_UB1.37 | length 35.2
  Top Layer w0.254: U53_UB1.5@77.8,71.113 84.245,71.113 v1(84.277,71.145) ; R321_UB1.1@100.99,75.692 102.108,75.692 102.692,76.276 102.692,77.292 103.124,77.724 105.689,77.724 106.063,77.35 U54_UB1.37@106.063,76.71
  Mid-Layer 2 w0.254: v1(84.277,71.145) 86.106,72.974 89.357,72.974 93.955,77.572 v1(103.022,77.572)
B_RDC_A0_UB2: R321_UB2.1 U53_UB2.5 U54_UB2.37 | length 30.6
  Top Layer w0.254: R321_UB2.1@148.376,74.02 148.499,74.142 v1(153.238,74.142) 154.067,74.142 154.092,74.168 U54_UB2.37@154.092,74.723 ; v1(169.164,75.921) 169.393,76.149 169.393,79.629 169.882,80.118 U53_UB2.5@172.745,80.118
  Mid-Layer 2 w0.254: v1(153.238,74.142) 153.289,74.193 154.102,74.193 154.407,73.889 165.481,73.889 167.335,75.743 168.986,75.743 v1(169.164,75.921)
B_RDC_A1_UB1: R323_UB1.1 U53_UB1.6 U54_UB1.36 | length 31.2
  Top Layer w0.254: U53_UB1.6@77.8,71.613 83.374,71.613 v1@83.731,71.971 ; R323_UB1.1@100.99,77.14 101.295,77.14 v1(102.362,78.207) 102.716,78.56 U54_UB1.36@104.213,78.56
  Mid-Layer 2 w0.254: v1@83.845,71.857 83.845,72.136 85.395,73.685 89.002,73.685 93.523,78.207 v1(102.362,78.207)
  other v1: 83.744,71.958
B_RDC_A1_UB2: R323_UB2.1 U53_UB2.6 U54_UB2.36 | length 28.3
  Top Layer w0.254: R323_UB2.1@148.401,75.539 148.488,75.539 149.523,76.573 U54_UB2.36@152.242,76.573 153.855,76.573 v1@153.899,76.53 ; v1(169.977,77.343) 170.002,77.368 170.002,77.493 170,77.495 170,79.043 170.576,79.618 U53_UB2.6@172.745,79.618
  Mid-Layer 2 w0.254: v1@153.873,76.53 154.991,75.413 164.414,75.413 166.345,77.343 169.848,77.343 170,77.495 170.002,77.493 170.002,77.368 v1(169.977,77.343)
  other v1: 153.848,76.479
B_RDC_A_UB1: R320_UB1.1 U54_UB1.29 | length 4.8
  Top Layer w0.254: R320_UB1.1@100.863,84.404 101.149,84.404 101.625,83.928 101.625,83.11 102.675,82.06 U54_UB1.29@104.213,82.06
B_RDC_A_UB2: R320_UB2.1 U54_UB2.29 | length 5.6
  Top Layer w0.254: R320_UB2.1@148.401,82.905 148.761,82.905 149.352,82.314 149.352,81.381 150.66,80.073 U54_UB2.29@152.242,80.073
B_RDC_B_UB1: R318_UB1.1 U54_UB1.30 | length 3.6
  Top Layer w0.254: R318_UB1.1@101.143,82.829 102.412,81.56 U54_UB1.30@104.213,81.56
B_RDC_B_UB2: R318_UB2.1 U54_UB2.30 | length 4.6
  Top Layer w0.254: R318_UB2.1@148.401,81.381 148.666,81.381 150.474,79.573 U54_UB2.30@152.242,79.573
B_RDC_CS_UB1: R327_UB1.1 U53_UB1.8 U54_UB1.2 | length 44.9
  Top Layer w0.254: U53_UB1.8@77.8,72.613 87.574,72.613 89.51,74.549 v1(89.51,76.429) ; v1(109.296,81.318) 109.296,81.001 111.236,79.06 U54_UB1.2@113.413,79.06 115.046,79.06 116.149,77.958 R327_UB1.1@116.434,77.958
  Mid-Layer 2 w0.254: v1(89.51,76.429) 92.71,79.629 97.409,79.629 99.098,81.318 v1(109.296,81.318)
B_RDC_CS_UB2: R327_UB2.1 U53_UB2.8 U54_UB2.2 | length 14.2
  Top Layer w0.254: U54_UB2.2@161.442,77.073 163.896,77.073 164.897,76.073 R327_UB2.1@165.354,76.073 ; v1(170.637,78.562) 170.815,78.562 170.871,78.618 U53_UB2.8@172.745,78.618
  Mid-Layer 2 w0.254: v1@163.982,77.013 165.557,78.588 170.84,78.588 170.815,78.562 v1(170.637,78.562)
  other v1: 164.033,76.937
B_RDC_DIR_UB1: RN17_UB1.5 U54_UB1.32 | length 3.2
  Top Layer w0.254: RN17_UB1.5@100.965,80.562 100.967,80.56 102.201,80.56 U54_UB1.32@104.213,80.56
B_RDC_DIR_UB2: RN17_UB2.5 U54_UB2.32 | length 4
  Top Layer w0.254: RN17_UB2.5@148.376,78.962 148.446,78.892 149.479,78.892 149.798,78.573 U54_UB2.32@152.242,78.573
B_RDC_DOS_UB1: RN17_UB1.1 U54_UB1.35 | length 3.3
  Top Layer w0.254: RN17_UB1.1@100.965,78.962 102.216,78.962 102.314,79.06 U54_UB1.35@104.213,79.06
B_RDC_DOS_UB2: RN17_UB2.1 U54_UB2.35 | length 4
  Top Layer w0.254: RN17_UB2.1@148.376,77.362 148.382,77.368 149.073,77.368 149.367,77.073 U54_UB2.35@152.242,77.073
B_RDC_FSYNC_UB1: U53_UB1.9 U54_UB1.4 | length 41.4
  Top Layer w0.254: U53_UB1.9@77.8,73.113 87.007,73.113 88.621,74.727 v1(88.621,76.454) ; v1(110.211,81.686) 110.211,81.178 111.329,80.06 U54_UB1.4@113.413,80.06
  Mid-Layer 2 w0.254: v1(88.621,76.454) 92.431,80.264 96.799,80.264 98.527,81.991 109.905,81.991 v1(110.211,81.686)
B_RDC_FSYNC_UB2: U53_UB2.9 U54_UB2.4 | length 13.5
  Top Layer w0.254: U54_UB2.4@161.442,78.073 162.935,78.073 v1(163.068,78.206) ; v1@171.094,77.8 171.412,78.118 U53_UB2.9@172.745,78.118
  Mid-Layer 2 w0.254: v1(163.068,78.206) 164.084,79.223 170.967,79.223 171.412,78.778 171.412,78.118 v1@171.094,77.8
  other v1: 171.094,77.927
B_RDC_LOT_UB1: RN17_UB1.3 U54_UB1.34 | length 3.3
  Top Layer w0.254: RN17_UB1.3@100.965,79.762 102.483,79.762 102.685,79.56 U54_UB1.34@104.213,79.56
B_RDC_LOT_UB2: RN17_UB2.3 U54_UB2.34 | length 4.1
  Top Layer w0.254: RN17_UB2.3@148.376,78.162 149.219,78.162 149.807,77.573 U54_UB2.34@152.242,77.573
B_RDC_NM_UB1: RN17_UB1.7 U54_UB1.31 | length 3.4
  Top Layer w0.254: RN17_UB1.7@100.993,81.391 RN17_UB1.7@100.965,81.363 101.933,81.363 102.235,81.06 U54_UB1.31@104.213,81.06
B_RDC_NM_UB2: RN17_UB2.7 U54_UB2.31 | length 4.2
  Top Layer w0.254: RN17_UB2.7@148.376,79.762 149.484,79.762 150.173,79.073 U54_UB2.31@152.242,79.073
B_RDC_RES0_UB1: R324_UB1.1 U53_UB1.2 U54_UB1.48 | length 45.6
  Top Layer w0.254: U53_UB1.2@77.8,69.613 85.438,69.613 v1(86.208,70.383) ; U54_UB1.48@111.563,76.71 111.563,77.273 111.582,77.292 113.513,77.292 113.64,77.165 113.64,75.768 114.498,74.91 R324_UB1.1@116.434,74.91
  Mid-Layer 2 w0.254: v1(86.208,70.383) 87.605,71.78 90.221,71.78 94.463,76.022 ; 94.437,76.022 94.463,76.022 ; v1@113.513,76.022 94.463,76.022
  other v1: 113.589,76.048
B_RDC_RES0_UB2: R324_UB2.1 U53_UB2.2 U54_UB2.48 | length 22.4
  Top Layer w0.254: U54_UB2.48@159.592,74.723 159.592,74.113 159.639,74.066 163.145,74.066 164.084,73.126 R324_UB2.1@165.354,73.126 ; v1(168.123,75.057) 168.123,80.569 169.172,81.618 U53_UB2.2@172.745,81.618
  Mid-Layer 2 w0.254: v1(164.084,73.101) 166.243,73.101 168.199,75.057 v1(168.123,75.057)
B_RDC_RES1_UB1: R326_UB1.1 U53_UB1.3 U54_UB1.1 | length 44.1
  Top Layer w0.254: U53_UB1.3@77.8,70.113 84.82,70.113 v1(85.192,70.485) ; U54_UB1.1@113.413,78.56 113.946,78.56 114.694,77.813 v1(114.694,77.356) 115.616,76.434 R326_UB1.1@116.434,76.434
  Mid-Layer 2 w0.254: v1(85.192,70.485) 87.071,72.365 89.814,72.365 94.285,76.835 114.173,76.835 v1(114.694,77.356)
B_RDC_RES1_UB2: R326_UB2.1 U53_UB2.3 U54_UB2.1 | length 18.1
  Top Layer w0.254: U54_UB2.1@161.442,76.573 162.161,76.573 v1(164.135,74.599) R326_UB2.1@165.354,74.599 ; v1@168.758,76.86 168.758,80.264 169.612,81.118 U53_UB2.3@172.745,81.118
  Mid-Layer 2 w0.254: v1(164.135,74.599) 164.642,74.599 166.522,76.479 168.351,76.479 168.732,76.86 v1(168.732,76.759)
B_RDC_RESET_UB1: R314_UB1.1 U53_UB1.14 U54_UB1.33 | length 32.8
  Top Layer w0.254: U53_UB1.14@77.8,75.613 84.554,75.613 84.861,75.921 v1(85.319,75.921) ; U54_UB1.33@104.213,80.06 105.633,80.06 v1(105.658,80.035)
  Mid-Layer 2 w0.254: v1(85.319,75.921) 85.598,75.641 89.865,75.641 93.082,78.858 98.289,78.858 99.466,80.035 v1(105.658,80.035)
  Bottom Layer w0.254: v1(105.658,80.035) 105.734,80.112 106.47,80.112 R314_UB1.1@106.877,80.518
B_RDC_RESET_UB2: R314_UB2.1 U53_UB2.14 U54_UB2.33 | length 25.2
  Top Layer w0.254: U54_UB2.33@152.242,78.073 153.93,78.073 154.026,77.978 v1(154.026,77.958) ; v1(170.612,76.496) 170.612,75.997 170.99,75.618 U53_UB2.14@172.745,75.618
  Mid-Layer 2 w0.254: v1(154.026,77.958) 160.904,77.958 162.509,76.352 164.377,76.352 166.028,78.003 170.143,78.003 170.637,77.509 v1@170.637,76.458 ; v1@170.584,76.523 v1(170.612,76.496)
  Bottom Layer w0.254: R314_UB2.1@152.705,78.054 153.929,78.054 v1(154.026,77.958)
B_RDC_SAMPLE_UB1: R329_UB1.1 U53_UB1.13 U54_UB1.10 | length 49
  Top Layer w0.254: U53_UB1.13@77.8,75.113 85.731,75.113 86.258,75.641 86.258,77.114 86.792,77.648 88.83,77.648 v1@90.145,78.962 ; v1(111.912,82.728) 112.245,83.06 U54_UB1.10@113.413,83.06 114.36,83.06 114.91,83.61 114.91,89.459 115.595,90.145 R329_UB1.1@116.332,90.145
  Mid-Layer 2 w0.254: v1(90.119,78.994) 91.973,80.848 96.241,80.848 98.12,82.728 v1@111.862,82.728
B_RDC_SAMPLE_UB2: R329_UB2.1 U53_UB2.13 U54_UB2.10 | length 33.5
  Top Layer w0.254: U54_UB2.10@161.442,81.073 162.659,81.073 162.763,81.178 v1(162.763,85.369) 162.763,85.431 R329_UB2.1@165.267,87.934 ; U53_UB2.13@172.745,76.118 175.762,76.118 v1(176.276,76.632)
  Mid-Layer 2 w0.254: v1(162.763,85.369) 166.446,85.369 168.808,83.007 171.831,83.007 175.133,83.007 176.759,81.382 176.759,77.114 v1(176.276,76.632)
B_RDC_SCLK_UB1: U53_UB1.12 U54_UB1.13 | length 40.9
  Top Layer w0.254: U53_UB1.12@77.8,74.613 86.063,74.613 87.046,75.596 v1@87.046,76.911 ; U54_UB1.13@111.563,85.91 111.563,84.804 v1(111.582,84.785)
  Mid-Layer 2 w0.254: v1(87.02,76.911) 87.02,77.267 87.782,78.029 87.782,79.4 91.389,83.007 94.31,83.007 96.088,84.785 v1(111.582,84.785)
B_RDC_SCLK_UB2: U53_UB2.12 U54_UB2.13 | length 24.9
  Top Layer w0.254: U54_UB2.13@159.592,83.923 159.592,83.333 159.614,83.312 161.696,83.312 v1(161.696,83.287) ; U53_UB2.12@172.745,76.618 175.145,76.618 v1(175.565,77.038)
  Mid-Layer 2 w0.254: v1(161.696,83.287) 163.398,83.287 164.211,82.474 170.815,82.474 171.97,81.318 175.158,81.318 176.073,80.404 176.073,77.546 v1(175.565,77.038)
B_RDC_SDI_UB1: U53_UB1.11 U54_UB1.12 | length 41.6
  Top Layer w0.254: U53_UB1.11@77.8,74.113 86.89,74.113 87.732,74.955 v1(87.732,76.352) ; v1(112.192,84.353) 112.485,84.06 U54_UB1.12@113.413,84.06
  Mid-Layer 2 w0.254: v1(87.732,76.352) 87.732,76.937 88.544,77.749 88.544,78.74 92.177,82.372 94.539,82.372 96.19,84.023 111.969,84.023 v1@112.172,84.226
B_RDC_SDI_UB2: U53_UB2.11 U54_UB2.12 | length 22.2
  Top Layer w0.254: v1(160.172,82.245) 160.344,82.073 U54_UB2.12@161.442,82.073 ; U53_UB2.11@172.745,77.118 174.451,77.118 v1(174.701,77.368)
  Mid-Layer 2 w0.254: v1(160.172,82.245) 160.299,82.118 162.916,82.118 163.195,81.839 170.522,81.839 172.579,79.781 175.108,79.781 175.438,79.451 175.438,78.105 v1(174.701,77.368)
B_RDC_SDO_UB1: U52_UB1.13 U54_UB1.11 | length 43.6
  Top Layer w0.254: v1(83.21,65.43) 83.23,65.411 U52_UB1.13@84.74,65.411 ; v1(87.909,70.866) 90.399,73.355 90.399,77.572 91.694,78.867 91.694,80.035 v1(93.142,81.483) ; v1@111.481,83.382 111.659,83.56 U54_UB1.11@113.413,83.56
  Mid-Layer 2 w0.254: v1(83.21,65.43) 84.633,65.43 85.369,66.167 85.369,68.326 v1@87.884,70.841 ; v1(93.142,81.483) 95.707,81.483 97.606,83.382 v1@111.481,83.382
  other v1: 111.481,83.439
B_RDC_SDO_UB2: U52_UB2.13 U54_UB2.11 | length 33.3
  Top Layer w0.254: v1(160.249,81.432) 160.39,81.573 U54_UB2.11@161.442,81.573 ; U52_UB2.13@174.848,65.806 176.854,65.806 177.292,66.243 v1(177.292,67.496)
  Mid-Layer 2 w0.254: v1(160.249,81.432) 162.636,81.432 162.966,81.102 170.078,81.102 171.983,79.197 171.983,72.034 174.269,69.748 176.936,69.748 177.292,69.393 v1(177.292,67.496)
B_REFOUT: C362_UB1.1 C363_UB1.1 C364_UB1.1 C365_UB1.1 R412.1 R416.1 R426.1 R428.1 U54_UB1.47 | length 61.6
  Top Layer w0.254: v1(111.404,78.113) 111.063,77.772 U54_UB1.47@111.063,76.71 111.063,75.703 111.709,75.057 112.573,75.057 ; C362_UB1.1@114.529,72.796 C362_UB1.1@114.529,73.101
  Top Layer w0.508: 112.573,75.057 112.725,75.057 113.71,74.072 ; C362_UB1.1@114.529,72.796 114.529,74.016 114.585,74.072 ; 115.214,74.072 113.71,74.072 ; R416.1@125.527,34.874 R412.1@125.527,36.424 125.527,37.008 124.257,38.278 124.257,46.584 125.405,47.732 R428.1@125.405,48.172 R426.1@125.405,49.721 125.405,51.48 124.282,52.603 124.282,70.383 120.574,74.092 118.599,74.092 118.579,74.072 117.438,74.072 117.418,74.092 117.024,74.092 117.004,74.072 115.863,74.072 115.843,74.092 113.73,74.092 113.71,74.072
  Bottom Layer w0.254: v1(111.404,78.113) 111.557,78.266 C363_UB1.1@111.557,78.969 C364_UB1.1@113.03,78.969
  Bottom Layer w0.508: v1(124.993,47.142) 125.425,47.574 C365_UB1.1@125.425,48.082
B_REFOUT_UB2: C362_UB2.1 C363_UB2.1 C364_UB2.1 C365_UB2.1 U54_UB2.47 | length 13
  Top Layer w0.254: v1(159.588,76.113) 159.092,75.617 U54_UB2.47@159.092,74.723 159.092,73.521 159.36,73.253 162.331,73.253 163.271,72.313 C362_UB2.1@163.271,71.018
  Bottom Layer w0.762: v1(159.588,76.113) 159.563,76.088 C363_UB2.1@159.563,74.854 C364_UB2.1@161.036,74.854 C365_UB2.1@162.509,74.854
B_SIN+': R409.2 U54_UB1.41 | length 51.1
  Top Layer w0.254: v1@108.063,74.879 U54_UB1.41@108.063,76.71
  Mid-Layer 2 w0.254: v1(107.95,74.879) 107.95,72.492 109.449,70.993 117.323,70.993 120.548,67.767 120.548,54.839 123.139,52.248 123.139,41.554 v1@125.095,39.599
  Bottom Layer w0.381: v1(125.12,39.573) 125.12,38.786 125.095,38.76 125.12,38.735 R409.2@126.543,38.735
B_SIN+'_UB2: R410.2 U54_UB2.41 | length 51.7
  Top Layer w0.254: v1(155.219,72.847) 155.194,72.872 155.169,72.872 156.092,73.796 U54_UB2.41@156.092,74.723
  Mid-Layer 2 w0.254: 133.325,43.561 133.325,42.24 ; v1(134.061,39.497) 133.718,39.84 133.718,41.846 133.325,42.24 ; v1(155.219,72.847) 148.463,72.847 133.325,57.709 133.325,42.24
  Bottom Layer w0.254: R410.2@132.944,38.837 133.401,38.837 v1(134.061,39.497)
B_SIN-': R187.2 U54_UB1.42 | length 47.9
  Top Layer w0.254: U54_UB1.42@108.563,76.71 108.563,75.384 108.699,75.248 ; v1@108.687,74.961 108.687,75.235
  Mid-Layer 2 w0.254: v1(108.687,74.879) 108.687,72.847 109.449,72.085 117.577,72.085 121.285,68.377 121.285,55.296 123.749,52.832 123.749,43.002 124.739,42.012 v1(125.146,42.012)
  Bottom Layer w0.381: v1(125.146,42.012) 126.39,42.012 R187.2@126.492,41.91
B_SIN-'_UB2: R417.2 U54_UB2.42 | length 48.9
  Top Layer w0.254: v1(156.083,72.771) 156.592,73.28 U54_UB2.42@156.592,74.723
  Mid-Layer 2 w0.254: v1@134.214,43.434 134.214,57.379 148.895,72.06 155.372,72.06 v1(156.083,72.771)
  Bottom Layer w0.254: R417.2@131.039,40.284 131.089,40.284 v1(134.239,43.434)
BC_COS+: R425.1 R426.2 U5.C5 | length 60.9
  Top Layer w0.254: R426.2@126.98,49.721 128.479,49.721 R425.1@128.529,49.772
  Mid-Layer 1 w0.254: U5.C5@114.7,-2.627 115.722,-1.605 115.722,2.286 117.856,4.42 v1(117.881,4.394)
  Mid-Layer 2 w0.254: 126.898,49.225 127.381,49.708 v1(127.711,49.708)
  Mid-Layer 2 w0.381: v1(117.881,4.394) 117.881,31.496 119.329,32.944 121.234,32.944 ; 121.437,33.147 121.234,32.944 ; 126.898,49.225 126.187,48.514 126.187,39.599 122.199,35.611 122.199,33.909 121.234,32.944
BC_COS+': C448.2 R25.1 R425.2 U69.5 | length 10.8
  Top Layer w0.254: R425.2@130.104,49.772 133.616,49.772 134.214,49.174 134.214,44.628 133.515,43.929 U69.5@132.593,43.929
BC_COS-: R428.2 R430.1 U5.B5 | length 61.6
  Top Layer w0.254: R428.2@126.98,48.172 128.479,48.172 R430.1@128.504,48.197
  Mid-Layer 2 w0.381: U5.B5@114.7,-4.627 115.697,-3.63 115.697,1.93 116.916,3.15 117.553,3.15 119.024,4.621 119.024,31.471 119.609,32.055 121.564,32.055 123.165,33.655 123.165,35.23 124.587,36.652 ; 124.587,36.271 124.587,36.652 ; v1(127.737,48.158) 126.924,47.346 126.924,38.989 124.587,36.652
BC_COS-': C448.1 R25.2 R430.2 U69.10 | length 9.9
  Top Layer w0.254: U69.10@126.447,43.954 126.46,43.967 128.295,43.967 130.079,45.751 R430.2@130.079,48.197 130.104,48.172 R25.2@131.628,48.172 C448.1@133.101,48.172
BC_E\X\C\: C445.2 U63.13 | length 8.6
  Top Layer w0.254: U63.13@126.314,79.832 127.762,79.832 128.6,78.994 128.6,75.641 128.041,75.082 C445.2@128.041,73.685 C445.2@128.321,73.965
BC_EXC: C441.2 U63.3 | length 6.4
  Top Layer w0.254: U63.3@132.486,78.562 133.401,78.562 133.934,78.029 133.934,75.184 C441.2@132.588,73.838
BC_EXCN: C446.1 R405.1 U5.E5 | length 67.6
  Top Layer w0.381: U5.E5@114.7,1.373 U5.E5@114.7,1.746
  Top Layer w0.762: R405.1@125.806,57.328 125.806,54.635 v2@127.432,53.01 ; C446.1@127.432,52.095 v2@127.432,53.01 ; v2@127.432,53.137 v2@127.432,53.01
  Mid-Layer 2 w0.381: U5.E5@114.7,1.373 114.7,1.924 115.773,2.997 115.773,34.087 v1(115.799,34.112)
  Mid-Layer 4 w0.381: v1(115.799,34.112) 117.551,35.865 119.075,35.865 122.098,35.865 123.317,37.084 ; 123.317,37.922 123.317,37.084 ; v2(127.406,53.137) 126.187,53.137 123.317,50.267 123.317,37.084
BC_EXCP: C440.1 R398.2 U5.D5 | length 74.4
  Top Layer w0.381: U5.D5@114.816,-0.627 U5.D5@114.7,-0.627 115.748,0.421 115.748,3.112 116.434,3.798 v1(116.434,3.988)
  Top Layer w0.762: C440.1@132.207,51.994 132.207,53.137 v2(132.182,53.162) 132.436,53.416 133.426,53.416 134.264,54.254 134.264,56.667 R398.2@133.629,57.302
  Mid-Layer 2 w0.381: v1(116.434,3.988) 116.688,4.242 116.688,31.902 116.561,32.029 116.561,33.757 v1(116.586,33.782)
  Mid-Layer 4 w0.381: v1(116.586,33.782) 117.729,34.925 122.453,34.925 124.181,36.652 ; 124.181,37.186 124.181,36.652 ; v2(132.182,53.162) 132.182,53.111 130.886,51.816 126.086,51.816 124.181,49.911 124.181,36.652
BC_SIN+: R411.1 R412.2 U5.C6 | length 46.3
  Top Layer w0.381: R412.2@127.102,36.424 127.115,36.437 R411.1@128.58,36.437
  Mid-Layer 1 w0.254: U5.C6@116.7,-2.627 117.729,-1.598 117.729,2.337 118.339,2.946 120.371,2.946 v1(121.717,4.293)
  Mid-Layer 2 w0.381: v1(121.717,4.293) 121.717,26.137 124.308,28.727 124.308,30.886 126.009,32.588 126.009,34.061 127.838,35.89 v1(127.838,36.398)
BC_SIN+': C447.2 R24.1 R411.2 U69.3 | length 10.5
  Top Layer w0.381: U69.3@132.593,41.389 130.67,41.389 129.667,40.386 129.667,37.998 130.155,37.51 R411.2@130.155,36.437 133.108,36.437 C447.2@133.121,36.424
BC_SIN-: R416.2 R418.1 U5.B6 | length 47.4
  Top Layer w0.381: R416.2@127.102,34.874 R418.1@128.6,34.874
  Mid-Layer 2 w0.381: U5.B6@116.7,-4.627 116.81,-4.627 117.704,-3.734 117.704,2.108 118.643,3.048 121.564,3.048 122.657,4.14 122.657,26.01 125.044,28.397 125.044,30.328 126.67,31.953 126.67,33.045 127.864,34.239 v1(127.864,34.849)
BC_SIN-': C447.1 R24.2 R418.2 U69.12 | length 13.2
  Top Layer w0.381: U69.12@126.447,41.364 128.486,41.364 128.765,41.084 128.765,37.626 v1(128.8,37.592) ; R418.2@130.175,34.874 v1(130.912,34.874) R24.2@131.648,34.874 133.096,34.874 C447.1@133.121,34.849
  Mid-Layer 2 w0.381: v1(128.8,37.592) 128.8,35.818 129.743,34.874 v1(130.912,34.874)
BC_SLT: R33.2 U63.9 U68.23 | length 47.6
  Top Layer w0.381: U63.9@126.314,84.912 v2(127.787,84.912) 128.397,84.912 129.311,85.827 134.116,85.827 134.874,86.585 134.874,99.72 133.985,100.609 133.985,105.232 131.826,107.391 v2@131.826,108.102 ; U68.23@134.904,112.32 U68.23@135.4,112.32 ; v2(136.576,110.566) 136.55,110.541 136.525,110.541 136.55,110.566 136.55,112.319 ; R33.2@139.065,112.293 138.709,112.293 138.684,112.319 136.55,112.319 ; R33.2@139.217,112.32 136.55,112.32 U68.23@135.4,112.32 ; U68.23@135.4,112.32 U68.23@135.4,112.32 136.55,112.319
  Mid-Layer 2 w0.381: v2(131.877,108.102) 132.385,108.61 134.62,108.61 v2(136.576,110.566)
BC_SLT_IN_UB1: U4_UB1.30 U55_UB1.13 | length 32.9
  Top Layer w0.254: U55_UB1.13@56.54,80.391 56.54,78.689 56.744,78.486 ; v1(70.282,86.284) 71.044,87.046 74.143,87.046 77.478,90.382 U4_UB1.30@81.585,90.382
  Mid-Layer 2 w0.254: v1(56.921,78.257) 57.074,78.257 57.48,78.664 57.48,80.797 58.395,81.712 65.405,81.712 69.977,86.284 v1(70.282,86.284)
BC_SLT_IN_UB2: U4_UB2.30 U55_UB2.13 | length 41
  Top Layer w0.254: U4_UB2.30@179.629,90.974 184.379,90.974 ; 185.471,90.957 185.454,90.974 184.379,90.974 ; v1(187.782,89.941) 186.749,90.974 184.379,90.974 ; v1(211.43,84.607) 211.633,84.607 213.385,82.855 U55_UB2.13@213.385,80.696
  Mid-Layer 2 w0.254: v1@187.757,89.713 191.16,86.309 191.987,86.309 192.063,86.385 208.331,86.385 208.737,85.979 208.737,85.115 209.245,84.607 v1@211.582,84.607
BC_SLT_UB1: P4_UB1.17 U4_UB1.19 U68.5 | length 69.9
  Top Layer w0.254: U4_UB1.19@89.205,90.382 91.55,90.382 92.735,91.567 92.735,118.745 ; 93.472,119.482 92.735,118.745 ; P4_UB1.17@100.533,125.853 99.843,125.853 92.735,118.745
  Top Layer w0.381: P4_UB1.17@100.533,125.853 102.239,125.853 104.978,123.114 115.9,123.114 ; 115.951,123.114 115.9,123.114 ; U68.5@123.8,117.12 121.894,117.12 115.9,123.114
BC_SLT_UB2: P4_UB2.17 U4_UB2.19 U68.27 | length 49.7
  Top Layer w0.254: P4_UB2.17@159.842,99.572 160.168,99.572 168.766,90.974 U4_UB2.19@172.009,90.974
  Top Layer w0.381: U68.27@135.4,115.52 145.135,115.52 154.457,106.197 154.457,101.194 155.829,99.822 159.592,99.822 P4_UB2.17@159.842,99.572
BC_SLTN: R31.2 U68.33 | length 5.2
  Top Layer w0.381: U68.33@135.4,120.32 138.582,120.32 139.7,121.437 R31.2@140.132,121.437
